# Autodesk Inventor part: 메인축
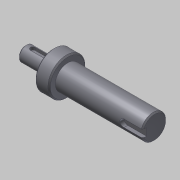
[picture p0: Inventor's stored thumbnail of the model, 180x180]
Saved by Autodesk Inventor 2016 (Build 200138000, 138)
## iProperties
Created: 2018-09
Part Number: 메인축
Document SubType Name: Modeling
Density: 7.86 g/cm^3
Material: 강철, 연강
Appearance: 강철
Mass: 251.954 g
Surface Area: 77.4403 cm^2
Volume: 32.0552 cm^3
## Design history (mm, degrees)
sketch "스케치1"
  geometry: L1 (34.997, -37.5)-(34.997, -77.5) reference; L2 (46.5, -38.401)-(46.5, -76.599) reference; L3 (12.497, -57.5)-(116.5, -57.5); L4 (12.497, -63.5)-(34.997, -63.5); L5 (34.997, -72.5)-(46.5, -72.5); L6 (46.5, -67.5)-(116.5, -67.5); L7 (116.5, -67.5)-(116.5, -57.5); L8 (12.497, -63.5)-(12.497, -57.5); 2 further points
  constraints: 12 end point, 5 point on line, 4 perpendicular, 1 midpoint, 1 parallel
  dimensions: "d0" = 20 diameter of L6 L3; "d1" = 30 diameter of L5 L3; "d2" = 22.5 distance of L4.start L4.end; "d3" = 70 distance of L6.start L6.end; "d5" = 12 diameter of L4 L3
revolve "회전1" sketch "스케치1" stored, may be unused: angle "d4" = 90 deg
chamfer "모따기1" distance "d6" = 1; stored, may be unused: second distance "d7" = 2, angle "d8" = 45 deg
node "작업 평면1"
sketch "스케치2"
  geometry: L1 (-11.25, -5)-(-11.25, 5) reference; L2 (-5.25, 2)-(4.75, 2); L3 (4.75, -2)-(-5.25, -2); A1 r 2 centre (4.75, 0) between (4.75, -2) and (4.75, 2); A2 r 2 centre (-5.25, 0) between (-5.25, 2) and (-5.25, -2); 2 further points
  constraints: 4 end point, 4 point on circle, 4 tangent, 2 centre point, 1 horizontal alignment, 1 midpoint, 1 parallel, 1 perpendicular
  dimensions: "d9" = 4 distance between parallel lines of L3 L2; "d10" = 14 dimension on A1 A2; "d11" = 4 distance edge to line of A2 L1
extrude "돌출1" cut sketch "스케치2" distance "d12" = 2.5; taper "d13" = 0 deg
node "작업 평면2"
sketch "스케치3"
  geometry: L1 (35, 9)-(35, -9) reference; L2 (35, 3)-(20, 3); L3 (20, -3)-(35, -3); A1 r 3 centre (20, 0) between (20, 3) and (20, -3); 2 further points
  constraints: 4 end point, 2 perpendicular, 2 point on circle, 2 point on line, 2 tangent, 1 centre point, 1 horizontal alignment, 1 midpoint
  dimensions: "d14" = 6 distance between parallel lines of L3 L2; "d15" = 18 dimension on A1 L1
extrude "돌출2" cut sketch "스케치3" distance "d16" = 3.5; taper "d17" = 0 deg
node "솔리드1"
node "참조1"
node "참조2"
